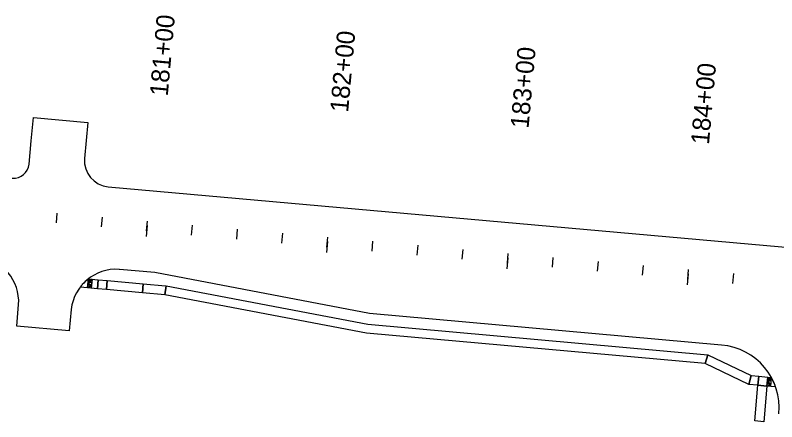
# Model space of a CAD drawing. Extents: x 20499216 to 20505321, y 7953487 to 7960535.
# Drawn here: x 20501735.9 to 20502156.3, y 7953785.2 to 7954010 of the extents above; entities that cross this region are included whole.
import ezdxf

# ---------------------------------------------------------------- set-up
doc = ezdxf.new("R2010")
doc.units = 0
for name, color, linetype in [('Drainage', 7, 'Continuous'), ('EXT_CU', 7, 'Continuous'), ('EXT_RR', 7, 'Continuous'), ('NamedBoundary', 7, 'Continuous'), ('Roadways', 7, 'Continuous'), ('Safety', 7, 'Continuous')]:
    doc.layers.add(name, color=color, linetype=linetype)

msp = doc.modelspace()

# ---------------------------------------------------------------- linework, layer by layer
at = {"layer": 'Drainage'}
for points in [[(20501776.27, 7953864.26), (20501775.83, 7953859.28), (20501771.71, 7953859.65)], [(20502155.68, 7953804.5), (20502150.89, 7953804.93), (20502151.34, 7953809.91), (20502153.33, 7953809.73)]]:
    msp.add_lwpolyline(points, dxfattribs=at)
for points in [[(20501781.64, 7953863.78), (20501781.2, 7953858.8), (20501775.83, 7953859.28), (20501776.27, 7953864.26)], [(20501806.54, 7953861.55), (20501806.1, 7953856.57), (20501786.18, 7953858.36), (20501786.62, 7953863.34)], [(20502142.28, 7953810.72), (20502140.93, 7953805.82), (20502116.87, 7953817.41), (20502118.22, 7953822.31)], [(20502142.28, 7953810.72), (20502146.36, 7953810.35), (20502145.91, 7953805.37), (20502140.93, 7953805.82)], [(20502144.15, 7953785.64), (20502145.91, 7953805.37), (20502150.89, 7953804.93), (20502149.13, 7953785.2)]]:
    msp.add_lwpolyline(points, close=True, dxfattribs=at)
for centre, radius, start, end in [((20501791.62, 7953844.53), 25, 127.8674, 138.5162), ((20501760.78, 7953868.09), 13.81, 322.3529, 322.7488), ((20501789.98, 7953845.88), 22.87, 138.3345, 142.7488), ((20502122.7, 7953792.8), 35, 19.5303, 28.9311)]:
    msp.add_arc(centre, radius, start, end, dxfattribs=at)
at = {"layer": 'EXT_CU'}
for p, q in [((20501775.83, 7953859.28), (20501776.27, 7953864.26)), ((20501776.27, 7953864.26), (20501778.26, 7953864.09)), ((20501778.26, 7953864.09), (20501777.82, 7953859.11)), ((20501777.82, 7953859.11), (20501775.83, 7953859.28)), ((20502150.89, 7953804.93), (20502151.34, 7953809.91)), ((20502151.34, 7953809.91), (20502153.33, 7953809.73)), ((20502153.33, 7953809.73), (20502152.88, 7953804.75)), ((20502152.88, 7953804.75), (20502150.89, 7953804.93))]:
    msp.add_line(p, q, dxfattribs=at)
msp.add_lwpolyline([(20501929.9, 7953834.16), (20501818.47, 7953855.47), (20501818.47, 7953855.47), (20501819.16, 7953860.42), (20501819.16, 7953860.42), (20501930.59, 7953839.11), (20502118.22, 7953822.31), (20502116.87, 7953817.41)], close=True, dxfattribs=at)
for centre, radius in [((20501776.41, 7953863.32), 0.0375), ((20501776.41, 7953863.32), 0.0187), ((20501776.45, 7953863.71), 0.0375), ((20501776.45, 7953863.71), 0.0187), ((20501776.48, 7953864.1), 0.0375), ((20501776.48, 7953864.1), 0.0187), ((20501776.8, 7953863.29), 0.0375), ((20501776.8, 7953863.29), 0.0187), ((20501776.84, 7953863.68), 0.0375), ((20501776.84, 7953863.68), 0.0187), ((20501776.87, 7953864.07), 0.0375), ((20501776.87, 7953864.07), 0.0187), ((20501777.19, 7953863.25), 0.0375), ((20501777.19, 7953863.25), 0.0187), ((20501777.23, 7953863.64), 0.0375), ((20501777.23, 7953863.64), 0.0187), ((20501777.26, 7953864.03), 0.0375), ((20501777.26, 7953864.03), 0.0187), ((20501777.58, 7953863.22), 0.0375), ((20501777.58, 7953863.22), 0.0187), ((20501777.62, 7953863.61), 0.0375), ((20501777.62, 7953863.61), 0.0187), ((20501777.65, 7953864), 0.0375), ((20501777.65, 7953864), 0.0187), ((20501777.97, 7953863.18), 0.0375), ((20501777.97, 7953863.18), 0.0187), ((20501778.01, 7953863.57), 0.0375), ((20501778.01, 7953863.57), 0.0187), ((20501778.04, 7953863.96), 0.0375), ((20501778.04, 7953863.96), 0.0187), ((20501776.06, 7953859.4), 0.0375), ((20501776.06, 7953859.4), 0.0187), ((20501776.09, 7953859.79), 0.0375), ((20501776.09, 7953859.79), 0.0187), ((20501776.13, 7953860.18), 0.0375), ((20501776.13, 7953860.18), 0.0187), ((20501776.17, 7953860.59), 0.0375), ((20501776.17, 7953860.59), 0.0187), ((20501776.2, 7953860.98), 0.0375), ((20501776.2, 7953860.98), 0.0187), ((20501776.24, 7953861.37), 0.0375), ((20501776.24, 7953861.37), 0.0187), ((20501776.27, 7953861.76), 0.0375), ((20501776.27, 7953861.76), 0.0187), ((20501776.31, 7953862.15), 0.0375), ((20501776.31, 7953862.15), 0.0187), ((20501776.34, 7953862.54), 0.0375), ((20501776.34, 7953862.54), 0.0187), ((20501776.38, 7953862.93), 0.0375), ((20501776.38, 7953862.93), 0.0187), ((20501776.45, 7953859.37), 0.0375), ((20501776.45, 7953859.37), 0.0187), ((20501776.48, 7953859.76), 0.0375), ((20501776.48, 7953859.76), 0.0187), ((20501776.52, 7953860.15), 0.0375), ((20501776.52, 7953860.15), 0.0187), ((20501776.56, 7953860.56), 0.0375), ((20501776.56, 7953860.56), 0.0187), ((20501776.59, 7953860.95), 0.0375), ((20501776.59, 7953860.95), 0.0187), ((20501776.63, 7953861.34), 0.0375), ((20501776.63, 7953861.34), 0.0187), ((20501776.66, 7953861.73), 0.0375), ((20501776.66, 7953861.73), 0.0187), ((20501776.7, 7953862.12), 0.0375), ((20501776.7, 7953862.12), 0.0187), ((20501776.73, 7953862.51), 0.0375), ((20501776.73, 7953862.51), 0.0187), ((20501776.77, 7953862.9), 0.0375), ((20501776.77, 7953862.9), 0.0187), ((20501776.84, 7953859.33), 0.0375), ((20501776.84, 7953859.33), 0.0187), ((20501776.87, 7953859.72), 0.0375), ((20501776.87, 7953859.72), 0.0187), ((20501776.91, 7953860.11), 0.0375), ((20501776.91, 7953860.11), 0.0187), ((20501776.95, 7953860.52), 0.0375), ((20501776.95, 7953860.52), 0.0187), ((20501776.98, 7953860.91), 0.0375), ((20501776.98, 7953860.91), 0.0187), ((20501777.02, 7953861.3), 0.0375), ((20501777.02, 7953861.3), 0.0187), ((20501777.05, 7953861.69), 0.0375), ((20501777.05, 7953861.69), 0.0187), ((20501777.09, 7953862.08), 0.0375), ((20501777.09, 7953862.08), 0.0187), ((20501777.12, 7953862.47), 0.0375), ((20501777.12, 7953862.47), 0.0187), ((20501777.16, 7953862.86), 0.0375), ((20501777.16, 7953862.86), 0.0187), ((20501777.23, 7953859.3), 0.0375), ((20501777.23, 7953859.3), 0.0187), ((20501777.26, 7953859.69), 0.0375), ((20501777.26, 7953859.69), 0.0187), ((20501777.3, 7953860.08), 0.0375), ((20501777.3, 7953860.08), 0.0187), ((20501777.34, 7953860.49), 0.0375), ((20501777.34, 7953860.49), 0.0187), ((20501777.37, 7953860.88), 0.0375), ((20501777.37, 7953860.88), 0.0187), ((20501777.41, 7953861.27), 0.0375), ((20501777.41, 7953861.27), 0.0187), ((20501777.44, 7953861.66), 0.0375), ((20501777.44, 7953861.66), 0.0187), ((20501777.48, 7953862.05), 0.0375), ((20501777.48, 7953862.05), 0.0187), ((20501777.51, 7953862.44), 0.0375), ((20501777.51, 7953862.44), 0.0187), ((20501777.55, 7953862.83), 0.0375), ((20501777.55, 7953862.83), 0.0187), ((20501777.62, 7953859.26), 0.0375), ((20501777.62, 7953859.26), 0.0187), ((20501777.65, 7953859.65), 0.0375), ((20501777.65, 7953859.65), 0.0187), ((20501777.69, 7953860.04), 0.0375), ((20501777.69, 7953860.04), 0.0187), ((20501777.73, 7953860.45), 0.0375), ((20501777.73, 7953860.45), 0.0187), ((20501777.76, 7953860.84), 0.0375), ((20501777.76, 7953860.84), 0.0187), ((20501777.8, 7953861.23), 0.0375), ((20501777.8, 7953861.23), 0.0187), ((20501777.83, 7953861.62), 0.0375), ((20501777.83, 7953861.62), 0.0187), ((20501777.87, 7953862.01), 0.0375), ((20501777.87, 7953862.01), 0.0187), ((20501777.9, 7953862.4), 0.0375), ((20501777.9, 7953862.4), 0.0187), ((20501777.94, 7953862.79), 0.0375), ((20501777.94, 7953862.79), 0.0187), ((20502151.44, 7953808.58), 0.0375), ((20502151.44, 7953808.58), 0.0187), ((20502151.48, 7953808.97), 0.0375), ((20502151.48, 7953808.97), 0.0187), ((20502151.51, 7953809.36), 0.0375), ((20502151.51, 7953809.36), 0.0187), ((20502151.55, 7953809.75), 0.0375), ((20502151.55, 7953809.75), 0.0187), ((20502151.83, 7953808.54), 0.0375), ((20502151.83, 7953808.54), 0.0187), ((20502151.87, 7953808.93), 0.0375), ((20502151.87, 7953808.93), 0.0187), ((20502151.9, 7953809.32), 0.0375), ((20502151.9, 7953809.32), 0.0187), ((20502151.94, 7953809.71), 0.0375), ((20502151.94, 7953809.71), 0.0187), ((20502152.22, 7953808.51), 0.0375), ((20502152.26, 7953808.9), 0.0375), ((20502152.26, 7953808.9), 0.0187), ((20502152.29, 7953809.29), 0.0375), ((20502152.29, 7953809.29), 0.0187), ((20502152.33, 7953809.68), 0.0375), ((20502152.33, 7953809.68), 0.0187), ((20502152.65, 7953808.86), 0.0375), ((20502152.65, 7953808.86), 0.0187), ((20502152.68, 7953809.25), 0.0375), ((20502152.68, 7953809.25), 0.0187), ((20502152.72, 7953809.64), 0.0375), ((20502152.72, 7953809.64), 0.0187), ((20502153.04, 7953808.83), 0.0375), ((20502153.04, 7953808.83), 0.0187), ((20502153.07, 7953809.22), 0.0375), ((20502153.07, 7953809.22), 0.0187), ((20502153.11, 7953809.61), 0.0375), ((20502153.11, 7953809.61), 0.0187), ((20502151.13, 7953805.04), 0.0375), ((20502151.13, 7953805.04), 0.0187), ((20502151.16, 7953805.43), 0.0375), ((20502151.16, 7953805.43), 0.0187), ((20502151.2, 7953805.82), 0.0375), ((20502151.2, 7953805.82), 0.0187), ((20502151.23, 7953806.23), 0.0375), ((20502151.23, 7953806.23), 0.0187), ((20502151.27, 7953806.62), 0.0375), ((20502151.27, 7953806.62), 0.0187), ((20502151.3, 7953807.02), 0.0375), ((20502151.3, 7953807.02), 0.0187), ((20502151.34, 7953807.41), 0.0375), ((20502151.34, 7953807.41), 0.0187), ((20502151.37, 7953807.8), 0.0375), ((20502151.37, 7953807.8), 0.0187), ((20502151.41, 7953808.19), 0.0375), ((20502151.41, 7953808.19), 0.0187), ((20502151.52, 7953805.01), 0.0375), ((20502151.52, 7953805.01), 0.0187), ((20502151.55, 7953805.4), 0.0375), ((20502151.55, 7953805.4), 0.0187), ((20502151.59, 7953805.79), 0.0375), ((20502151.59, 7953805.79), 0.0187), ((20502151.62, 7953806.2), 0.0375), ((20502151.62, 7953806.2), 0.0187), ((20502151.66, 7953806.59), 0.0375), ((20502151.66, 7953806.59), 0.0187), ((20502151.69, 7953806.98), 0.0375), ((20502151.69, 7953806.98), 0.0187), ((20502151.73, 7953807.37), 0.0375), ((20502151.73, 7953807.37), 0.0187), ((20502151.76, 7953807.76), 0.0375), ((20502151.76, 7953807.76), 0.0187), ((20502151.8, 7953808.15), 0.0375), ((20502151.8, 7953808.15), 0.0187), ((20502151.91, 7953804.97), 0.0375), ((20502151.91, 7953804.97), 0.0187), ((20502151.94, 7953805.36), 0.0375), ((20502151.94, 7953805.36), 0.0187), ((20502151.98, 7953805.75), 0.0375), ((20502151.98, 7953805.75), 0.0187), ((20502152.01, 7953806.17), 0.0375), ((20502152.01, 7953806.17), 0.0187), ((20502152.05, 7953806.56), 0.0375), ((20502152.05, 7953806.56), 0.0187), ((20502152.08, 7953806.95), 0.0375), ((20502152.08, 7953806.95), 0.0187), ((20502152.12, 7953807.34), 0.0375), ((20502152.12, 7953807.34), 0.0187), ((20502152.15, 7953807.73), 0.0375), ((20502152.15, 7953807.73), 0.0187), ((20502152.19, 7953808.12), 0.0375), ((20502152.19, 7953808.12), 0.0187), ((20502152.22, 7953808.51), 0.0187), ((20502152.3, 7953804.94), 0.0375), ((20502152.3, 7953804.94), 0.0187), ((20502152.33, 7953805.33), 0.0375), ((20502152.33, 7953805.33), 0.0187), ((20502152.37, 7953805.72), 0.0375), ((20502152.37, 7953805.72), 0.0187), ((20502152.4, 7953806.13), 0.0375), ((20502152.4, 7953806.13), 0.0187), ((20502152.44, 7953806.52), 0.0375), ((20502152.44, 7953806.52), 0.0187), ((20502152.47, 7953806.91), 0.0375), ((20502152.47, 7953806.91), 0.0187), ((20502152.51, 7953807.3), 0.0375), ((20502152.51, 7953807.3), 0.0187), ((20502152.54, 7953807.69), 0.0375), ((20502152.54, 7953807.69), 0.0187), ((20502152.58, 7953808.08), 0.0375), ((20502152.58, 7953808.08), 0.0187), ((20502152.61, 7953808.47), 0.0375), ((20502152.61, 7953808.47), 0.0187), ((20502152.69, 7953804.9), 0.0375), ((20502152.69, 7953804.9), 0.0187), ((20502152.72, 7953805.29), 0.0375), ((20502152.72, 7953805.29), 0.0187), ((20502152.76, 7953805.68), 0.0375), ((20502152.76, 7953805.68), 0.0187), ((20502152.79, 7953806.1), 0.0375), ((20502152.79, 7953806.1), 0.0187), ((20502152.83, 7953806.49), 0.0375), ((20502152.83, 7953806.49), 0.0187), ((20502152.86, 7953806.88), 0.0375), ((20502152.86, 7953806.88), 0.0187), ((20502152.9, 7953807.27), 0.0375), ((20502152.9, 7953807.27), 0.0187), ((20502152.93, 7953807.66), 0.0375), ((20502152.93, 7953807.66), 0.0187), ((20502152.97, 7953808.05), 0.0375), ((20502152.97, 7953808.05), 0.0187), ((20502153, 7953808.44), 0.0375), ((20502153, 7953808.44), 0.0187)]:
    msp.add_circle(centre, radius, dxfattribs=at)
at = {"layer": 'EXT_RR'}
for p, q in [((20501758.58, 7953895.18), (20501759.07, 7953900.62)), ((20501783.48, 7953892.95), (20501783.97, 7953898.39)), ((20501808.66, 7953893.77), (20501808.11, 7953887.67)), ((20501833.28, 7953888.49), (20501833.77, 7953893.93)), ((20501858.18, 7953886.26), (20501858.67, 7953891.7)), ((20501883.08, 7953884.03), (20501883.57, 7953889.47)), ((20501908.26, 7953884.85), (20501907.71, 7953878.75)), ((20501932.88, 7953879.57), (20501933.37, 7953885.01)), ((20501957.79, 7953877.34), (20501958.27, 7953882.78)), ((20501982.69, 7953875.11), (20501983.17, 7953880.55)), ((20502007.86, 7953875.93), (20502007.31, 7953869.83)), ((20502032.49, 7953870.65), (20502032.97, 7953876.09)), ((20502057.39, 7953868.42), (20502057.87, 7953873.86)), ((20502082.29, 7953866.19), (20502082.77, 7953871.63)), ((20502107.46, 7953867.01), (20502106.91, 7953860.92)), ((20502132.09, 7953861.73), (20502132.57, 7953867.17))]:
    msp.add_line(p, q, dxfattribs=at)
at = {"layer": 'NamedBoundary'}
for points in [[(20501743.48, 7953927.61), (20501744.7, 7953940.56), (20501745.91, 7953953.5), (20501775.93, 7953950.79), (20501774.15, 7953930.8)], [(20501787.19, 7953915.21), (20502204.56, 7953877.83), (20502491.63, 7953852.83)], [(20502125.82, 7953827.66), (20501931.42, 7953845.06), (20501812.97, 7953867.72), (20501793.53, 7953869.46), (20501793.23, 7953869.49)], [(20501766.77, 7953847.38), (20501765.71, 7953835.53), (20501736.68, 7953838.13), (20501737.74, 7953849.98)]]:
    msp.add_lwpolyline(points, dxfattribs=at)
for centre, radius, start, end in [((20501788.47, 7953929.52), 14.37, 174.9256, 264.8834), ((20501735.01, 7953928.41), 8.5, 264.8834, 354.618), ((20501712.76, 7953851.57), 25.03, 356.3606, 83.4061), ((20501791.64, 7953844.51), 25.03, 86.3606, 173.4061), ((20502122.7, 7953792.8), 35, 354.8834, 84.8834)]:
    msp.add_arc(centre, radius, start, end, dxfattribs=at)
at = {"layer": 'Roadways'}
for points in [[(20501786.62, 7953863.34), (20501786.18, 7953858.36), (20501781.2, 7953858.8), (20501781.64, 7953863.78)], [(20501818.91, 7953860.45), (20501819.16, 7953860.42), (20501818.47, 7953855.47), (20501806.1, 7953856.57), (20501806.54, 7953861.55)], [(20502145.91, 7953805.37), (20502146.36, 7953810.35), (20502151.34, 7953809.91), (20502150.89, 7953804.93)]]:
    msp.add_lwpolyline(points, close=True, dxfattribs=at)
at = {"layer": 'Safety'}
for p, q in [((20501808.38, 7953890.72), (20501808.87, 7953896.16)), ((20501907.98, 7953881.8), (20501908.47, 7953887.24)), ((20502007.59, 7953872.88), (20502008.07, 7953878.32)), ((20502107.19, 7953863.96), (20502107.67, 7953869.4))]:
    msp.add_line(p, q, dxfattribs=at)

# ---------------------------------------------------------------- texts
at = {"layer": 'EXT_RR'}
for s, p in [('181+00', (20501820.06, 7953964.97)), ('182+00', (20501919.66, 7953956.05)), ('183+00', (20502019.26, 7953947.14)), ('184+00', (20502118.87, 7953938.22))]:
    msp.add_text(s, height=10.02, rotation=84.8834, dxfattribs=at).set_placement(p)

doc.saveas('drawing.dxf')
